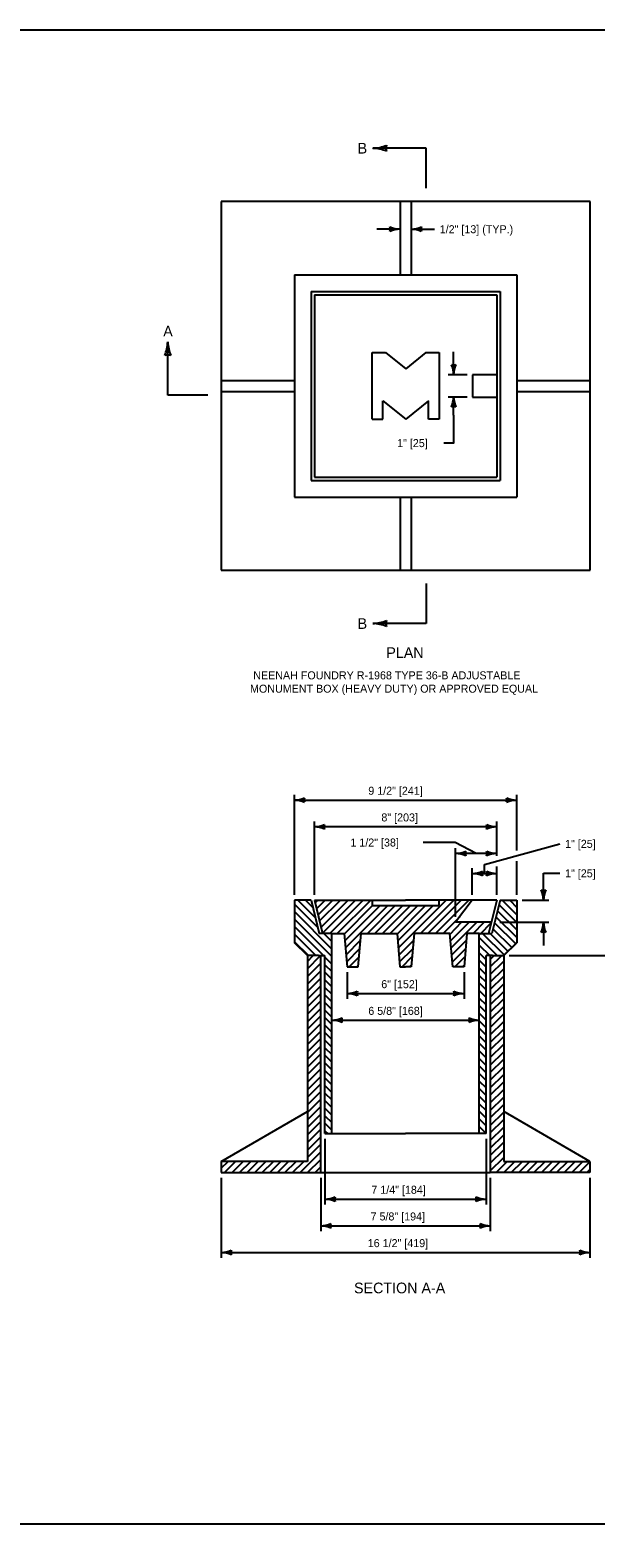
# Model space of a CAD drawing. Extents: x 49991.4 to 50021, y 49987.6 to 50011.4.
# Drawn here: x 50006.72 to 50010.95, y 49987.8 to 49999 of the extents above; entities that cross this region are included whole.
import ezdxf

# ---------------------------------------------------------------- set-up
doc = ezdxf.new("R2010")
doc.units = 0
for name, color, linetype in [('Level 1', 7, 'Continuous'), ('Level 2', 7, 'Continuous'), ('Level 3', 7, 'Continuous'), ('Level 6', 7, 'Continuous')]:
    doc.layers.add(name, color=color, linetype=linetype)

msp = doc.modelspace()

# ---------------------------------------------------------------- linework, layer by layer
at = {"layer": 'Level 1'}
for p, q in [((50008.152, 49997.712), (50008.152, 49994.949)), ((50010.915, 49997.712), (50008.152, 49997.712)), ((50009.492, 49997.712), (50009.492, 49997.164)), ((50009.575, 49997.712), (50009.575, 49997.164)), ((50010.915, 49994.949), (50010.915, 49997.712)), ((50008.7, 49997.164), (50008.7, 49995.497)), ((50008.7, 49997.164), (50010.367, 49997.164)), ((50010.367, 49997.164), (50010.367, 49995.497)), ((50008.825, 49997.039), (50008.825, 49995.622)), ((50008.825, 49997.039), (50010.242, 49997.039)), ((50010.242, 49997.039), (50010.242, 49995.622)), ((50008.85, 49997.014), (50008.85, 49995.647)), ((50008.85, 49997.014), (50010.217, 49997.014)), ((50010.217, 49997.014), (50010.217, 49995.647)), ((50009.284, 49996.331), (50009.284, 49996.581)), ((50009.284, 49996.581), (50009.384, 49996.581)), ((50009.384, 49996.581), (50009.534, 49996.459)), ((50009.684, 49996.581), (50009.534, 49996.459)), ((50009.684, 49996.581), (50009.784, 49996.581)), ((50009.784, 49996.581), (50009.784, 49996.081)), ((50008.152, 49996.372), (50008.7, 49996.372)), ((50010.217, 49996.414), (50010.034, 49996.414)), ((50010.034, 49996.414), (50010.034, 49996.247)), ((50010.367, 49996.372), (50010.915, 49996.372)), ((50008.152, 49996.289), (50008.7, 49996.289)), ((50009.284, 49996.081), (50009.284, 49996.331)), ((50010.034, 49996.247), (50010.217, 49996.247)), ((50010.367, 49996.289), (50010.915, 49996.289)), ((50009.364, 49996.081), (50009.364, 49996.219)), ((50009.364, 49996.219), (50009.534, 49996.081)), ((50009.704, 49996.219), (50009.534, 49996.081)), ((50009.704, 49996.081), (50009.704, 49996.219)), ((50009.284, 49996.081), (50009.364, 49996.081)), ((50009.784, 49996.081), (50009.704, 49996.081)), ((50008.825, 49995.622), (50010.242, 49995.622)), ((50008.85, 49995.647), (50010.217, 49995.647)), ((50008.7, 49995.497), (50010.367, 49995.497)), ((50009.492, 49995.497), (50009.492, 49994.949)), ((50009.575, 49995.497), (50009.575, 49994.949)), ((50008.152, 49994.949), (50010.915, 49994.949)), ((50008.825, 49992.476), (50008.7, 49992.476)), ((50008.7, 49992.476), (50008.7, 49992.157)), ((50008.7, 49992.447), (50008.876, 49992.271)), ((50008.727, 49992.476), (50008.857, 49992.346)), ((50008.784, 49992.476), (50008.838, 49992.422)), ((50008.825, 49992.476), (50008.887, 49992.226)), ((50008.85, 49992.476), (50008.912, 49992.226)), ((50008.85, 49992.476), (50009.533, 49992.476)), ((50008.855, 49992.455), (50008.876, 49992.476)), ((50008.866, 49992.41), (50008.932, 49992.476)), ((50008.878, 49992.365), (50008.989, 49992.476)), ((50008.889, 49992.32), (50009.045, 49992.476)), ((50008.9, 49992.274), (50009.102, 49992.476)), ((50008.911, 49992.229), (50009.158, 49992.476)), ((50008.965, 49992.226), (50009.215, 49992.476)), ((50009.022, 49992.226), (50009.272, 49992.476)), ((50009.074, 49992.222), (50009.286, 49992.435)), ((50009.079, 49992.17), (50009.343, 49992.435)), ((50009.083, 49992.118), (50009.4, 49992.435)), ((50009.248, 49992.226), (50009.456, 49992.435)), ((50009.283, 49992.476), (50009.283, 49992.435)), ((50009.283, 49992.435), (50009.783, 49992.435)), ((50009.304, 49992.226), (50009.513, 49992.435)), ((50009.361, 49992.226), (50009.569, 49992.435)), ((50009.418, 49992.226), (50009.626, 49992.435)), ((50009.47, 49992.222), (50009.682, 49992.435)), ((50009.474, 49992.17), (50009.739, 49992.435)), ((50009.479, 49992.118), (50009.837, 49992.476)), ((50010.216, 49992.476), (50009.533, 49992.476)), ((50009.644, 49992.226), (50009.894, 49992.476)), ((50009.7, 49992.226), (50009.95, 49992.476)), ((50009.757, 49992.226), (50010.007, 49992.476)), ((50009.783, 49992.476), (50009.783, 49992.435)), ((50010.033, 49992.476), (50009.908, 49992.31)), ((50010.216, 49992.476), (50010.154, 49992.226)), ((50010.241, 49992.476), (50010.179, 49992.226)), ((50010.233, 49992.443), (50010.366, 49992.309)), ((50010.241, 49992.476), (50010.366, 49992.476)), ((50010.256, 49992.476), (50010.366, 49992.366)), ((50010.313, 49992.476), (50010.366, 49992.422)), ((50010.366, 49992.476), (50010.366, 49992.157)), ((50008.7, 49992.391), (50008.981, 49992.109)), ((50008.7, 49992.334), (50008.981, 49992.053)), ((50009.814, 49992.226), (50009.942, 49992.354)), ((50010.21, 49992.352), (50010.366, 49992.196)), ((50010.222, 49992.397), (50010.366, 49992.253)), ((50008.7, 49992.278), (50008.918, 49992.06)), ((50008.7, 49992.221), (50008.861, 49992.06)), ((50008.981, 49992.226), (50008.887, 49992.226)), ((50008.921, 49992.226), (50008.981, 49992.166)), ((50008.977, 49992.226), (50008.981, 49992.223)), ((50008.981, 49990.726), (50008.981, 49992.226)), ((50008.981, 49992.226), (50009.074, 49992.226)), ((50009.074, 49992.226), (50009.096, 49991.976)), ((50009.179, 49991.976), (50009.201, 49992.226)), ((50009.201, 49992.226), (50009.47, 49992.226)), ((50009.47, 49992.226), (50009.491, 49991.976)), ((50009.597, 49992.226), (50009.575, 49991.976)), ((50009.865, 49992.226), (50009.597, 49992.226)), ((50009.887, 49991.976), (50009.865, 49992.226)), ((50009.866, 49992.222), (50009.953, 49992.31)), ((50009.87, 49992.17), (50010.01, 49992.31)), ((50009.875, 49992.118), (50010.067, 49992.31)), ((50010.175, 49992.31), (50009.908, 49992.31)), ((50009.993, 49992.226), (50009.971, 49991.976)), ((50010.085, 49992.226), (50009.993, 49992.226)), ((50010.04, 49992.226), (50010.123, 49992.31)), ((50010.085, 49990.726), (50010.085, 49992.226)), ((50010.085, 49992.226), (50010.179, 49992.226)), ((50010.085, 49992.217), (50010.094, 49992.226)), ((50010.096, 49992.226), (50010.173, 49992.303)), ((50010.11, 49992.226), (50010.273, 49992.064)), ((50010.153, 49992.226), (50010.154, 49992.228)), ((50010.167, 49992.226), (50010.301, 49992.092)), ((50010.188, 49992.262), (50010.329, 49992.12)), ((50010.199, 49992.307), (50010.358, 49992.148)), ((50008.7, 49992.164), (50008.805, 49992.06)), ((50008.798, 49992.06), (50008.7, 49992.157)), ((50009.088, 49992.066), (50009.196, 49992.175)), ((50009.092, 49992.014), (50009.191, 49992.113)), ((50009.484, 49992.066), (50009.592, 49992.174)), ((50009.488, 49992.014), (50009.587, 49992.112)), ((50009.879, 49992.066), (50009.988, 49992.174)), ((50009.884, 49992.014), (50009.983, 49992.112)), ((50010.085, 49992.195), (50010.22, 49992.06)), ((50010.085, 49992.138), (50010.164, 49992.06)), ((50010.267, 49992.06), (50010.366, 49992.159)), ((50010.269, 49992.06), (50010.366, 49992.157)), ((50008.881, 49992.06), (50008.798, 49992.06)), ((50008.798, 49992.06), (50008.798, 49990.518)), ((50008.798, 49992.017), (50008.84, 49992.06)), ((50008.798, 49991.96), (50008.897, 49992.06)), ((50008.798, 49991.904), (50008.898, 49992.004)), ((50008.881, 49992.06), (50008.929, 49992.06)), ((50008.898, 49990.435), (50008.898, 49992.06)), ((50008.929, 49990.726), (50008.929, 49992.06)), ((50008.929, 49992.048), (50008.981, 49991.996)), ((50008.929, 49991.992), (50008.981, 49991.94)), ((50009.111, 49991.976), (50009.185, 49992.051)), ((50009.168, 49991.976), (50009.18, 49991.989)), ((50009.507, 49991.976), (50009.581, 49992.05)), ((50009.564, 49991.976), (50009.576, 49991.988)), ((50009.903, 49991.976), (50009.977, 49992.05)), ((50009.96, 49991.976), (50009.972, 49991.988)), ((50010.085, 49992.081), (50010.137, 49992.029)), ((50010.085, 49992.025), (50010.137, 49991.973)), ((50010.185, 49992.06), (50010.137, 49992.06)), ((50010.137, 49990.726), (50010.137, 49992.06)), ((50010.168, 49992.06), (50010.168, 49990.435)), ((50010.168, 49992.032), (50010.196, 49992.06)), ((50010.168, 49991.975), (50010.253, 49992.06)), ((50010.168, 49991.918), (50010.269, 49992.019)), ((50010.185, 49992.06), (50010.269, 49992.06)), ((50010.269, 49992.06), (50010.269, 49990.518)), ((50008.798, 49991.847), (50008.898, 49991.947)), ((50008.798, 49991.79), (50008.898, 49991.89)), ((50008.929, 49991.935), (50008.981, 49991.883)), ((50008.929, 49991.879), (50008.981, 49991.827)), ((50009.096, 49991.976), (50009.179, 49991.976)), ((50009.491, 49991.976), (50009.533, 49991.976)), ((50009.575, 49991.976), (50009.533, 49991.976)), ((50009.971, 49991.976), (50009.887, 49991.976)), ((50010.085, 49991.968), (50010.137, 49991.916)), ((50010.085, 49991.912), (50010.137, 49991.86)), ((50010.168, 49991.862), (50010.269, 49991.962)), ((50010.168, 49991.805), (50010.269, 49991.905)), ((50008.798, 49991.734), (50008.898, 49991.834)), ((50008.798, 49991.677), (50008.898, 49991.777)), ((50008.929, 49991.822), (50008.981, 49991.77)), ((50008.929, 49991.766), (50008.981, 49991.714)), ((50010.085, 49991.855), (50010.137, 49991.803)), ((50010.085, 49991.799), (50010.137, 49991.747)), ((50010.168, 49991.749), (50010.269, 49991.849)), ((50010.168, 49991.692), (50010.269, 49991.792)), ((50008.798, 49991.621), (50008.898, 49991.721)), ((50008.798, 49991.564), (50008.898, 49991.664)), ((50008.929, 49991.709), (50008.981, 49991.657)), ((50008.929, 49991.652), (50008.981, 49991.6)), ((50010.085, 49991.742), (50010.137, 49991.69)), ((50010.085, 49991.685), (50010.137, 49991.633)), ((50010.168, 49991.636), (50010.269, 49991.736)), ((50010.168, 49991.579), (50010.269, 49991.679)), ((50008.798, 49991.508), (50008.898, 49991.608)), ((50008.798, 49991.451), (50008.898, 49991.551)), ((50008.929, 49991.596), (50008.981, 49991.544)), ((50008.929, 49991.539), (50008.981, 49991.487)), ((50010.085, 49991.629), (50010.137, 49991.577)), ((50010.085, 49991.572), (50010.137, 49991.52)), ((50010.168, 49991.522), (50010.269, 49991.623)), ((50010.168, 49991.466), (50010.269, 49991.566)), ((50008.798, 49991.394), (50008.898, 49991.495)), ((50008.798, 49991.338), (50008.898, 49991.438)), ((50008.929, 49991.483), (50008.981, 49991.431)), ((50008.929, 49991.426), (50008.981, 49991.374)), ((50010.085, 49991.516), (50010.137, 49991.464)), ((50010.085, 49991.459), (50010.137, 49991.407)), ((50010.168, 49991.409), (50010.269, 49991.509)), ((50010.168, 49991.353), (50010.269, 49991.453)), ((50008.798, 49991.281), (50008.898, 49991.381)), ((50008.798, 49991.225), (50008.898, 49991.325)), ((50008.929, 49991.37), (50008.981, 49991.318)), ((50008.929, 49991.313), (50008.981, 49991.261)), ((50010.085, 49991.403), (50010.137, 49991.351)), ((50010.085, 49991.346), (50010.137, 49991.294)), ((50010.168, 49991.296), (50010.269, 49991.396)), ((50010.168, 49991.24), (50010.269, 49991.34)), ((50008.798, 49991.168), (50008.898, 49991.268)), ((50008.798, 49991.112), (50008.898, 49991.212)), ((50008.929, 49991.256), (50008.981, 49991.204)), ((50008.929, 49991.2), (50008.981, 49991.148)), ((50010.085, 49991.289), (50010.137, 49991.237)), ((50010.085, 49991.233), (50010.137, 49991.181)), ((50010.168, 49991.183), (50010.269, 49991.283)), ((50010.168, 49991.126), (50010.269, 49991.227)), ((50008.798, 49991.055), (50008.898, 49991.155)), ((50008.798, 49990.998), (50008.898, 49991.099)), ((50008.929, 49991.143), (50008.981, 49991.091)), ((50008.929, 49991.087), (50008.981, 49991.035)), ((50010.085, 49991.176), (50010.137, 49991.124)), ((50010.085, 49991.12), (50010.137, 49991.068)), ((50010.168, 49991.07), (50010.269, 49991.17)), ((50010.168, 49991.013), (50010.269, 49991.113)), ((50008.798, 49990.942), (50008.898, 49991.042)), ((50008.798, 49990.885), (50008.898, 49990.985)), ((50008.929, 49991.03), (50008.981, 49990.978)), ((50008.929, 49990.974), (50008.981, 49990.922)), ((50010.085, 49991.063), (50010.137, 49991.011)), ((50010.085, 49991.007), (50010.137, 49990.955)), ((50010.168, 49990.957), (50010.269, 49991.057)), ((50010.168, 49990.9), (50010.269, 49991)), ((50008.152, 49990.518), (50008.798, 49990.891)), ((50008.798, 49990.829), (50008.898, 49990.929)), ((50008.798, 49990.772), (50008.898, 49990.872)), ((50008.929, 49990.917), (50008.981, 49990.865)), ((50008.929, 49990.86), (50008.981, 49990.808)), ((50010.085, 49990.95), (50010.137, 49990.898)), ((50010.085, 49990.894), (50010.137, 49990.841)), ((50010.168, 49990.844), (50010.269, 49990.944)), ((50010.168, 49990.787), (50010.269, 49990.887)), ((50010.914, 49990.518), (50010.269, 49990.891)), ((50008.798, 49990.716), (50008.898, 49990.816)), ((50008.798, 49990.659), (50008.898, 49990.759)), ((50008.929, 49990.804), (50008.981, 49990.752)), ((50008.929, 49990.747), (50008.95, 49990.726)), ((50010.085, 49990.837), (50010.137, 49990.785)), ((50010.085, 49990.78), (50010.137, 49990.728)), ((50010.168, 49990.731), (50010.269, 49990.831)), ((50010.168, 49990.674), (50010.269, 49990.774)), ((50008.798, 49990.603), (50008.898, 49990.703)), ((50008.798, 49990.546), (50008.898, 49990.646)), ((50008.929, 49990.726), (50008.981, 49990.726)), ((50008.981, 49990.726), (50009.533, 49990.726)), ((50010.085, 49990.726), (50009.533, 49990.726)), ((50010.137, 49990.726), (50010.085, 49990.726)), ((50010.168, 49990.617), (50010.269, 49990.717)), ((50010.168, 49990.561), (50010.269, 49990.661)), ((50008.743, 49990.435), (50008.898, 49990.589)), ((50008.799, 49990.435), (50008.898, 49990.533)), ((50010.168, 49990.504), (50010.269, 49990.604)), ((50010.168, 49990.448), (50010.269, 49990.548)), ((50008.798, 49990.518), (50008.152, 49990.518)), ((50008.152, 49990.518), (50008.152, 49990.435)), ((50008.152, 49990.466), (50008.204, 49990.518)), ((50008.152, 49990.435), (50008.898, 49990.435)), ((50008.177, 49990.435), (50008.26, 49990.518)), ((50008.234, 49990.435), (50008.317, 49990.518)), ((50008.29, 49990.435), (50008.374, 49990.518)), ((50008.347, 49990.435), (50008.43, 49990.518)), ((50008.403, 49990.435), (50008.487, 49990.518)), ((50008.46, 49990.435), (50008.543, 49990.518)), ((50008.516, 49990.435), (50008.6, 49990.518)), ((50008.573, 49990.435), (50008.656, 49990.518)), ((50008.63, 49990.435), (50008.713, 49990.518)), ((50008.686, 49990.435), (50008.77, 49990.518)), ((50008.856, 49990.435), (50008.898, 49990.476)), ((50008.898, 49990.435), (50010.168, 49990.435)), ((50010.914, 49990.435), (50010.168, 49990.435)), ((50010.212, 49990.435), (50010.295, 49990.518)), ((50010.268, 49990.435), (50010.352, 49990.518)), ((50010.269, 49990.518), (50010.914, 49990.518)), ((50010.325, 49990.435), (50010.408, 49990.518)), ((50010.382, 49990.435), (50010.465, 49990.518)), ((50010.438, 49990.435), (50010.521, 49990.518)), ((50010.495, 49990.435), (50010.578, 49990.518)), ((50010.551, 49990.435), (50010.635, 49990.518)), ((50010.608, 49990.435), (50010.691, 49990.518)), ((50010.664, 49990.435), (50010.748, 49990.518)), ((50010.721, 49990.435), (50010.804, 49990.518)), ((50010.778, 49990.435), (50010.861, 49990.518)), ((50010.834, 49990.435), (50010.914, 49990.515)), ((50010.891, 49990.435), (50010.914, 49990.458)), ((50010.914, 49990.518), (50010.914, 49990.435))]:
    msp.add_line(p, q, dxfattribs=at)
msp.add_lwpolyline([(49999.384, 49998.999), (50016.75, 49998.999), (50016.75, 49987.799), (49999.384, 49987.799)], close=True, dxfattribs=at)
at = {"layer": 'Level 3'}
for p, q in [((50009.492, 49997.505), (50009.319, 49997.505)), ((50009.575, 49997.505), (50009.749, 49997.505)), ((50009.893, 49996.414), (50009.893, 49996.587)), ((50009.994, 49996.414), (50009.853, 49996.414)), ((50009.994, 49996.247), (50009.853, 49996.247)), ((50009.893, 49996.111), (50009.893, 49996.247)), ((50008.7, 49992.516), (50008.7, 49993.266)), ((50008.7, 49993.226), (50010.366, 49993.226)), ((50010.366, 49992.849), (50010.366, 49993.266)), ((50008.85, 49992.516), (50008.85, 49993.066)), ((50010.216, 49993.026), (50008.85, 49993.026)), ((50010.216, 49992.808), (50010.216, 49993.066)), ((50009.905, 49992.908), (50009.665, 49992.908)), ((50010.062, 49992.826), (50009.905, 49992.908)), ((50009.908, 49992.35), (50009.908, 49992.866)), ((50010.216, 49992.826), (50009.908, 49992.826)), ((50010.366, 49992.516), (50010.366, 49992.769)), ((50010.033, 49992.516), (50010.033, 49992.716)), ((50010.033, 49992.676), (50010.216, 49992.676)), ((50010.125, 49992.676), (50010.125, 49992.742)), ((50010.216, 49992.516), (50010.216, 49992.728)), ((50010.566, 49992.476), (50010.566, 49992.677)), ((50010.566, 49992.677), (50010.688, 49992.677)), ((50010.406, 49992.476), (50010.606, 49992.476)), ((50010.24, 49992.31), (50010.606, 49992.31)), ((50010.566, 49992.31), (50010.566, 49992.136)), ((50010.309, 49992.06), (50011.114, 49992.06)), ((50009.096, 49991.936), (50009.096, 49991.736)), ((50009.971, 49991.936), (50009.971, 49991.736)), ((50009.096, 49991.776), (50009.971, 49991.776)), ((50008.981, 49991.576), (50010.085, 49991.576)), ((50008.929, 49990.686), (50008.929, 49990.195)), ((50010.137, 49990.686), (50010.137, 49990.195)), ((50008.152, 49990.395), (50008.152, 49989.795)), ((50008.898, 49990.395), (50008.898, 49989.995)), ((50010.168, 49990.395), (50010.168, 49989.995)), ((50010.914, 49990.395), (50010.914, 49989.795)), ((50008.929, 49990.235), (50010.137, 49990.235)), ((50008.898, 49990.035), (50010.168, 49990.035)), ((50008.152, 49989.835), (50010.914, 49989.835))]:
    msp.add_line(p, q, dxfattribs=at)
for points in [[(50009.893, 49996.111), (50009.893, 49995.902), (50009.821, 49995.902)], [(50010.125, 49992.742), (50010.688, 49992.898)]]:
    msp.add_lwpolyline(points, dxfattribs=at)
for centre, radius, start, end in [((50009.273, 49998.422), 0.311, 272.8273, 292.0772), ((50009.276, 49997.816), 0.296, 67.456, 87.6395), ((50009.459, 49998.112), 0.073, 162.1388, 197.8612), ((50009.501, 49997.727), 0.222, 247.456, 267.6395), ((50009.364, 49997.505), 0.0548, 342.1388, 17.8612), ((50009.504, 49997.272), 0.233, 92.8273, 112.0772), ((50009.564, 49997.738), 0.233, 272.8273, 292.0772), ((50009.566, 49997.283), 0.222, 67.456, 87.6395), ((50009.704, 49997.505), 0.0548, 162.1388, 197.8612), ((50009.893, 49996.542), 0.0548, 252.1388, 287.8612), ((50009.661, 49996.402), 0.233, 2.8273, 22.0772), ((50010.115, 49996.405), 0.222, 157.456, 177.6395), ((50009.671, 49996.256), 0.222, 337.456, 357.6395), ((50010.126, 49996.259), 0.233, 182.8273, 202.0772), ((50009.893, 49996.119), 0.0548, 72.1388, 107.8612), ((50009.276, 49994.845), 0.296, 272.3605, 292.544), ((50009.459, 49994.549), 0.073, 162.1388, 197.8612), ((50009.273, 49994.239), 0.311, 67.9228, 87.1727), ((50008.688, 49993.459), 0.233, 272.8273, 292.0772), ((50008.691, 49993.004), 0.222, 67.456, 87.6395), ((50008.828, 49993.226), 0.0548, 162.1388, 197.8612), ((50010.376, 49993.448), 0.222, 247.456, 267.6395), ((50010.238, 49993.226), 0.0548, 342.1388, 17.8612), ((50010.378, 49992.993), 0.233, 92.8273, 112.0772), ((50008.838, 49993.259), 0.233, 272.8273, 292.0772), ((50008.841, 49992.804), 0.222, 67.456, 87.6395), ((50008.978, 49993.026), 0.0548, 162.1388, 197.8612), ((50010.226, 49993.248), 0.222, 247.456, 267.6395), ((50010.088, 49993.026), 0.0548, 342.1388, 17.8612), ((50010.228, 49992.793), 0.233, 92.8273, 112.0772), ((50009.897, 49993.059), 0.233, 272.8273, 292.0772), ((50009.899, 49992.604), 0.222, 67.456, 87.6395), ((50010.036, 49992.826), 0.0548, 162.1388, 197.8612), ((50010.226, 49993.048), 0.222, 247.456, 267.6395), ((50010.088, 49992.826), 0.0548, 342.1388, 17.8612), ((50010.228, 49992.593), 0.233, 92.8273, 112.0772), ((50010.022, 49992.909), 0.233, 272.8273, 292.0772), ((50010.024, 49992.454), 0.222, 67.456, 87.6395), ((50010.161, 49992.676), 0.0548, 162.1388, 197.8612), ((50010.226, 49992.898), 0.222, 247.456, 267.6395), ((50010.088, 49992.676), 0.0548, 342.1388, 17.8612), ((50010.228, 49992.443), 0.233, 92.8273, 112.0772), ((50010.566, 49992.604), 0.0548, 252.1388, 287.8612), ((50010.334, 49992.465), 0.233, 2.8273, 22.0772), ((50010.789, 49992.467), 0.222, 157.456, 177.6395), ((50010.344, 49992.319), 0.222, 337.456, 357.6395), ((50010.566, 49992.181), 0.0548, 72.1388, 107.8612), ((50010.799, 49992.321), 0.233, 182.8273, 202.0772), ((50009.084, 49992.009), 0.233, 272.8273, 292.0772), ((50009.086, 49991.554), 0.222, 67.456, 87.6395), ((50009.224, 49991.776), 0.0548, 162.1388, 197.8612), ((50009.98, 49991.998), 0.222, 247.456, 267.6395), ((50009.842, 49991.776), 0.0548, 342.1388, 17.8612), ((50009.982, 49991.543), 0.233, 92.8273, 112.0772), ((50008.97, 49991.809), 0.233, 272.8273, 292.0772), ((50008.972, 49991.354), 0.222, 67.456, 87.6395), ((50009.109, 49991.576), 0.0548, 162.1388, 197.8612), ((50010.094, 49991.798), 0.222, 247.456, 267.6395), ((50009.957, 49991.576), 0.0548, 342.1388, 17.8612), ((50010.097, 49991.343), 0.233, 92.8273, 112.0772), ((50008.917, 49990.467), 0.233, 272.8273, 292.0772), ((50008.92, 49990.012), 0.222, 67.456, 87.6395), ((50009.057, 49990.235), 0.0548, 162.1388, 197.8612), ((50010.146, 49990.457), 0.222, 247.456, 267.6395), ((50010.009, 49990.235), 0.0548, 342.1388, 17.8612), ((50010.149, 49990.002), 0.233, 92.8273, 112.0772), ((50008.886, 49990.267), 0.233, 272.8273, 292.0772), ((50008.889, 49989.812), 0.222, 67.456, 87.6395), ((50009.026, 49990.035), 0.0548, 162.1388, 197.8612), ((50010.178, 49990.257), 0.222, 247.456, 267.6395), ((50010.04, 49990.035), 0.0548, 342.1388, 17.8612), ((50010.18, 49989.802), 0.233, 92.8273, 112.0772), ((50008.14, 49990.067), 0.233, 272.8273, 292.0772), ((50008.28, 49989.835), 0.0548, 162.1388, 197.8612), ((50010.924, 49990.057), 0.222, 247.456, 267.6395), ((50010.786, 49989.835), 0.0548, 342.1388, 17.8612), ((50008.143, 49989.612), 0.222, 67.456, 87.6395), ((50010.926, 49989.602), 0.233, 92.8273, 112.0772)]:
    msp.add_arc(centre, radius, start, end, dxfattribs=at)
at = {"layer": 'Level 6'}
for p, q in [((50009.688, 49998.112), (50009.288, 49998.112)), ((50009.688, 49997.812), (50009.688, 49998.112)), ((50007.752, 49996.261), (50007.752, 49996.661)), ((50008.052, 49996.261), (50007.752, 49996.261)), ((50009.688, 49994.849), (50009.688, 49994.549)), ((50009.688, 49994.549), (50009.288, 49994.549))]:
    msp.add_line(p, q, dxfattribs=at)
for centre, radius, start, end in [((50007.456, 49996.673), 0.296, 337.456, 357.6395), ((50008.063, 49996.676), 0.311, 182.8273, 202.0772), ((50007.752, 49996.49), 0.073, 72.1388, 107.8612)]:
    msp.add_arc(centre, radius, start, end, dxfattribs=at)

# ---------------------------------------------------------------- texts
at = {"layer": 'Level 2'}
for s, height, p in [('B', 0.08, (50009.174, 49998.072)), ('1/2" [13] (TYP.)', 0.06, (50009.789, 49997.475)), ('A', 0.08, (50007.718, 49996.701)), ('1" [25]', 0.06, (50009.47, 49995.872)), ('B', 0.08, (50009.174, 49994.509)), ('PLAN', 0.08, (50009.389, 49994.291)), ('NEENAH FOUNDRY R-1968 TYPE 36-B ADJUSTABLE', 0.06, (50008.392, 49994.131)), ('MONUMENT BOX (HEAVY DUTY) OR APPROVED EQUAL', 0.06, (50008.368, 49994.031)), ('9 1/2" [241]', 0.06, (50009.254, 49993.266)), ('8" [203]', 0.06, (50009.352, 49993.066)), ('1 1/2" [38]', 0.06, (50009.12, 49992.878)), ('1" [25]', 0.06, (50010.728, 49992.868)), ('1" [25]', 0.06, (50010.728, 49992.647)), ('6" [152]', 0.06, (50009.351, 49991.816)), ('6 5/8" [168]', 0.06, (50009.254, 49991.616)), ('7 1/4" [184]', 0.06, (50009.277, 49990.275)), ('7 5/8" [194]', 0.06, (50009.271, 49990.075)), ('16 1/2" [419]', 0.06, (50009.25, 49989.875)), ('SECTION A-A', 0.08, (50009.147, 49989.529))]:
    msp.add_text(s, height=height, dxfattribs=at).set_placement(p)

doc.saveas('drawing.dxf')
